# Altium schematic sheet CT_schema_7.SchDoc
size 278 x 170 mm
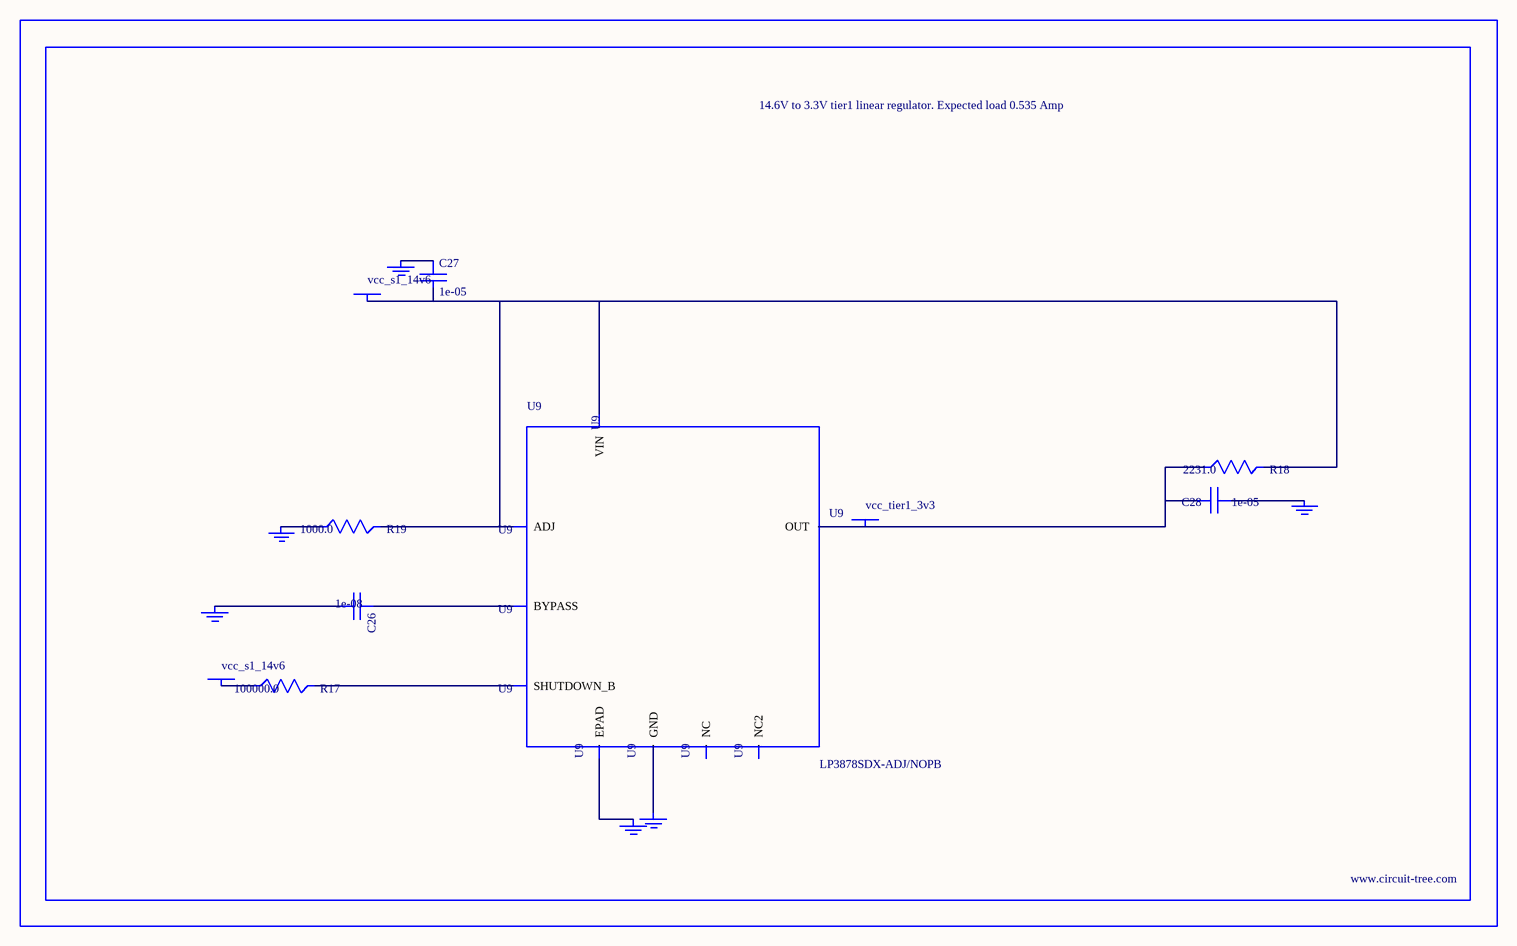
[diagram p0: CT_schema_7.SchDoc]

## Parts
BORDER6  (no value)
C26  1e-08  [C0402]
C27  1e-05  [C1210]
C28  1e-05  [C1210]
GND_INSTANCE_6_0  (no value)
GND_INSTANCE_6_1  (no value)
GND_INSTANCE_6_2  (no value)
GND_INSTANCE_6_3  (no value)
GND_INSTANCE_6_4  (no value)
GND_INSTANCE_6_5  (no value)
POWER_INSTANCE_6_0  vcc_s1_14v6
POWER_INSTANCE_6_1  vcc_s1_14v6
POWER_INSTANCE_6_2  vcc_tier1_3v3
R17  100000.0  [R0603]
R18  2231.0  [R0603]
R19  1000.0  [R0603]
U9  LP3878SDX-ADJ/NOPB  [WSON-8]

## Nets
NetC26_1: C26.1 U9.1(BYPASS)
NetC26_2: C26.2 GND_INSTANCE_6_0.0(GND)
NetC27_1: C27.1 GND_INSTANCE_6_1.0(GND)
NetC27_2: C27.2 POWER_INSTANCE_6_0.0(PWR) R18.2 R19.2 U9.4(VIN) U9.6(ADJ)
NetC28_1: C28.1 GND_INSTANCE_6_2.0(GND)
NetC28_2: C28.2 POWER_INSTANCE_6_2.0(PWR) R18.1 U9.5(OUT)
NetGND_INSTANCE_6_3_0: GND_INSTANCE_6_3.0(GND) R19.1
NetGND_INSTANCE_6_4_0: GND_INSTANCE_6_4.0(GND) U9.PAD(EPAD)
NetGND_INSTANCE_6_5_0: GND_INSTANCE_6_5.0(GND) U9.3(GND)
NetPOWER_INSTANCE_6_1_0: POWER_INSTANCE_6_1.0(PWR) R17.1
NetR17_2: R17.2 U9.8(SHUTDOWN_B)

Not connected (* = marked no-connect by the designer): U9 2(NC) 7(NC2)

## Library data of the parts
BORDER6 = BORDER_PAGE6
C26 = C0402C103K3RAC
C27 = C1210C106K5PACTU
C28 = GRM32DR61E106MA12L
GND_INSTANCE_6_0-GND_INSTANCE_6_5 = GND
POWER_INSTANCE_6_0-POWER_INSTANCE_6_2 = PWR
R17 = RC0603JR-07100KL
R18 = R18
R19 = RC0603JR-071KL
